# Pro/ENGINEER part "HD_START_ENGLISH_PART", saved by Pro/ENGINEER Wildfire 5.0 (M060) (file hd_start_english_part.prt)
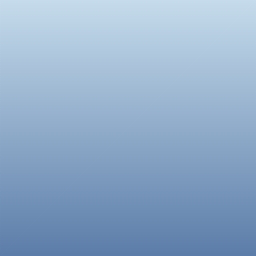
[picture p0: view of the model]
Units: Inch lbm Second (Pro/E Default); INCH, POUND, SECS

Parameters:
  DRW_UNITS = "ENGLISH"
  TOL_NAME = "INCHES"
  SUR = "250"

Other named items: CS_DEF, PT_ORIG, SIDE, TOP, FRONT

Layers: ANNOT, AXES, COSMETIC, CS, CURVES, DATUMS, DEF_CS, DEF_DATUMS, GEOM_CRVS, GEOM_DATUMS, GEOM_PNTS, PTS, SURFS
